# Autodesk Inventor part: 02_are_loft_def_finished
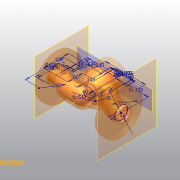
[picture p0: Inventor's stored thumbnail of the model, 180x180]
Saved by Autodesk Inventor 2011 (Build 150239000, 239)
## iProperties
Created: 2002-07
Part Number: 02_are_loft_def_finished
Document SubType Name: Modeling
Designer: Lieven Grauls
Stock Number: 02_are_loft_def_finished
Project: Valve Techcamp 2008
Density: 1 g/cm^3
Surface Area: 777.103 cm^2
Company: Autodesk
Control State: 0
Master: False
Checked Out: False
Shininess: 64.0
Length Units: 11269
Angle Units: 11279
Time Units: 11290
Mass Units: 11283
Length Display Precision: 3
Angle Display Precision: 2
Density: 0.0
Volumn: 0.0
Area: 0.0
PropertySet Name: Model Information
Author: Lieven Grauls
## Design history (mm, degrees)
sketch "Sketch2"
  geometry: L1 (-130, 0)-(-120, 0); L2 (130, 0)-(120, 0); L3 (38.866, 33.5)-(18.866, 33.5); L4 (-50, 103)-(50, 103); L5 (0, -118.6)-(0, 151.6) reference; L6 (-40.156, -25)-(0, -25); A1 r 80 centre (-120, -80) between (-74.375, -14.286) and (-120, 0); A2 r 60 centre (-40.156, 35) between (-74.375, -14.286) and (-40.156, -25); A3 r 70 centre (120, 70) between (70.614, 20.391) and (120, 0); A4 r 45 centre (38.866, -11.5) between (70.614, 20.391) and (38.866, 33.5); 4 further points
  constraints: 10 end point, 8 point on circle, 6 tangent, 4 centre point, 3 horizontal, 2 horizontal alignment, 2 perpendicular, 2 point on line, 1 midpoint, 1 other
  dimensions: "d8" = 130 distance of L1.start point (0, 0); "d9" = 80 radius of A1; "d10" = 60 radius of A2; "d15" = 130 distance of L2.start point (0, 0) (= d8); "d16" = 70 radius of A3; "d61" = 33.5 distance of the line from the sketch origin of L3; "d63" = 45 radius of A4; "d102" = 10 distance of L1.start L1.end; "d103" = 10 distance of L2.start L2.end; "d182" = 20 distance of L3.start L3.end; "d220" = 103 distance of the line from the sketch origin of L4; "d221" = 100 distance of L4.start L4.end; "d249" = 25 distance of the line from the sketch origin of L6
workplane "Work Plane6"
workplane "Work Plane2"
workplane "Work Plane1"
sketch "Sketch5"
  geometry: C1 r 25.5 at (0, 0); 1 further point
  constraints: 1 centre point, 1 coincident
  dimensions: "d24" = 51 diameter of C1
sketch "Sketch6"
  geometry: C1 r 25.5 at (0, 0); 1 further point
  constraints: 1 centre point, 1 coincident
  dimensions: "d25" = 51 diameter of C1
sketch "Sketch11"
  geometry: C1 r 25.5 at (0, 0); 1 further point
  constraints: 1 centre point, 1 coincident
  dimensions: "d104" = 51 diameter of C1 (= d24)
sketch "Sketch7"
  geometry: L1 (0, -22.6)-(0, 135.6) reference; L2 (-32.5, 103)-(-32.5, 74); L3 (-32.5, 74)-(-45.093, 69.417); L4 (-32.5, 8)-(0, 8); L5 (0, 103)-(-32.5, 103); L6 (-46.873, 22.579)-(-39.053, 11.411); L7 (-183.58, 0)-(30.597, 0) reference; A1 r 18 centre (-38.936, 52.502) between (-45.093, 69.417) and (-56.906, 51.462); A2 r 56 centre (-1, 54.699) between (-56.906, 51.462) and (-46.873, 22.579); A3 r 8 centre (-32.5, 16) between (-39.053, 11.411) and (-32.5, 8); 1 further point
  constraints: 10 end point, 6 point on circle, 5 point on line, 5 tangent, 3 centre point, 2 perpendicular, 1 horizontal, 1 parallel
  dimensions: "d28" = 65 diameter of L2 L1; "d30" = 110 deg angle of L2 L3; "d31" = 18 radius of A1; "d32" = 56 radius of A2; "d41" = 55 deg angle of L4 L6; "d65" = 8 radius of A3; "d135" = 103 distance between parallel lines of L7 L5; "d136" = 29 distance of L2.start L2.end; "d137" = 8 distance between parallel lines of L7 L4; "d138" = 1 distance from line of A2.centre L1; "d139" = 65 diameter of A3.centre L1
workplane "Work Plane5"
sketch "Sketch14"
  geometry: L1 (-102.1, 0)-(56.1, 0) reference; L2 (-15, -32)-(-15, 32); L3 (15, 25)-(15, -25); A1 r 56 centre (-12.302, 18.948) between (-9.774, -36.995) and (10.217, -32.325); A2 r 56 centre (-12.302, -18.948) between (10.217, 32.325) and (-9.774, 36.995); A3 r 5 centre (-10, 32) between (-9.774, 36.995) and (-15, 32); A4 r 5 centre (-10, -32) between (-15, -32) and (-9.774, -36.995); A5 r 8 centre (7, 25) between (15, 25) and (10.217, 32.325); A6 r 8 centre (7, -25) between (10.217, -32.325) and (15, -25); 2 further points
  constraints: 12 point on circle, 8 tangent, 6 centre point, 4 end point, 3 equal radius, 1 parallel, 1 perpendicular
  dimensions: "d144" = 15 distance from line of point (0, 0) L2 (= 0.5 x d145); "d145" = 30 distance between parallel lines of L2 L3; "d146" = 56 radius of A1; "d147" = 5 radius of A3; "d148" = 64 distance of A3.centre A4.centre; "d149" = 32 distance from line of L1 A4.centre (= 0.5 x d148); "d150" = 50 distance of A5.centre A6.centre; "d151" = 25 distance from line of L1 A6.centre (= 0.5 x d150); "d152" = 8 radius of A5
workplane "Work Plane10"
sketch "Sketch17"
  geometry: L1 (-9, 25.5)-(-15.5, 32); L2 (-15.5, 32)-(-16.5, 32); L3 (-9, 25.5)-(-9, 0); L4 (-88.753, 0)-(146.625, 0) reference; L5 (0, -7.725)-(0, 46.353) reference; A1 r 32 centre (-16.5, 0) between (-16.5, 32) and (-48.5, 0)
  constraints: 6 end point, 3 point on line, 2 perpendicular, 2 point on circle, 1 centre point, 1 tangent
  dimensions: "d250" = 32 radius of A1; "d252" = 45 deg angle of L3 L1; "d253" = 1 distance of L1.end L2.end; "d286" = 9 distance between parallel lines of L5 L3; "d287" = 25.5 distance from line of L4 L1.start
revolve "Revolution6" sketch "Sketch17" stored, may be unused: angle "d255" = 180 deg
sketch "Sketch19"
  geometry: L1 (32, 1)-(32, 0) reference; L2 (25.5, 7.5)-(32, 1) reference; L3 (-25.5, 7.5)-(25.5, 7.5) reference; L4 (-32, 1)-(-25.5, 7.5) reference; L5 (-32, 0)-(-32, 1) reference; A1 r 32 centre (0, 0) between (-32, 0) and (32, 0) reference; 1 further point
extrude "Extrusion4" join sketch "Sketch19" distance "d257" = 26; taper "d258" = 0 deg
fillet "Fillet11" dims "d259" = 8
extrude "Extrusion5" join sketch "Sketch11" stored distance "d260" = 30; taper "d261" = 0 deg
extrude "Extrusion2" join sketch "Sketch5" distance "d159" = 10; taper "d160" = 0 deg
loft "Loft4" dims "d262" = 10, "d264" = 15, "d266" = 0, "d267" = 90 deg, "d268" = 0, "d269" = 0, "d270" = 204.28206, "d271" = 10, "d272" = 104.55731, "d273" = 10, "d274" = 204.01489, "d275" = 10, "d276" = 61.38852, "d277" = 5.87128, "d278" = 204.19995, "d279" = 9.945, "d280" = 36.81128, "d281" = 3.52068, "d282" = 204.19997, "d283" = 9.95821, "d318" = 90 deg, "d319" = 90 deg, "d320" = 20.91146, "d321" = 2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
  node "Edges4"
  node "Edges5"
extrude "Extrusion3" join sketch "Sketch6" distance "d183" = 10; taper "d184" = 0 deg
loft "Loft3" dims "d187" = 0, "d191" = 0, "d192" = 0, "d193" = 204.28206, "d194" = 10, "d195" = 110.06209, "d196" = 10, "d197" = 220, "d198" = 10.56486, "d199" = 55.03105, "d200" = 5, "d201" = 210, "d202" = 10.0143, "d207" = 10, "d208" = 90 deg, "d209" = 90 deg, "d213" = 0, "d214" = 90 deg
  node "Edges3"
feature "OffsetSrf1" dims "d203" = 8, "d204" = 8
feature "OffsetSrf2" dims "d205" = 8, "d206" = 8
revolve "Revolution5" stored, may be unused: angle "d212" = 90 deg
fillet "Fillet8" dims "d215" = 5
fillet "Fillet13" dims "d311" = 5
sketch "Sketch1"
  geometry: L1 (70, 103)-(70, 55); L2 (57.702, 15.997)-(40.477, -8.604); L3 (0, -42.404)-(0, 138.901) reference; L4 (28.19, -15)-(15, -15); L5 (-198.18, 0)-(118.199, 0) reference; L6 (-198.18, 103)-(118.199, 103) reference; A1 r 68 centre (2, 55) between (57.702, 15.997) and (70, 55); A2 r 15 centre (28.19, 0) between (28.19, -15) and (40.477, -8.604); 1 further point
  constraints: 6 end point, 4 point on circle, 4 tangent, 2 centre point, 1 perpendicular, 1 point on line
  dimensions: "d1" = 140 diameter of L1 L3; "d4" = 68 radius of A1; "d5" = 35 deg angle of L1 L2; "d217" = 15 distance between parallel lines of L4 L5; "d218" = 15 radius of A2; "d222" = 48 distance of L1.start L1.end; "d229" = 15 distance from line of L3 L4.end
feature "RevolutionSrf1" dims angle "d219" = 90 deg
sketch "Sketch8"
  geometry: L1 (-130, 85.5)-(-110, 85.5); L2 (-130, 85.5)-(-132.392, 17.012); L3 (-110, 85.5)-(-108.763, 14.622); L4 (-183.58, 0)-(30.597, 0) reference; L5 (-130, 135.6)-(-130, -22.6) reference
  constraints: 6 end point, 1 parallel, 1 point on line
  dimensions: "d47" = 20 distance of L1.start L1.end; "d223" = 92 deg angle of L4 L2; "d226" = 171 diameter of L1 L4; "d227" = 91 deg angle of L1 L3
feature "RevolutionSrf2" sketch "Sketch8" dims angle "d228" = 90 deg
mirror "Mirror1"
delete_face "Delete Face1"
sketch "Sketch15"
  geometry: L1 (-80, 100)-(-46.5, 100); L2 (-37.013, 96.7)-(-37.013, 60); L3 (-37.013, 60)-(-35.513, 60); L4 (-80, 113)-(-80, 100); L5 (-46.5, 100)-(-46.5, 96.7); L6 (-46.5, 96.7)-(-37.013, 96.7); L7 (0, -22.6)-(0, 135.6) reference; L8 (-183.58, 0)-(30.597, 0) reference; L9 (-35.513, 60)-(-35.513, 0); L10 (-35.513, 0)-(0, 0)
  constraints: 16 end point, 4 perpendicular, 2 vertical, 1 collinear, 1 horizontal, 1 parallel, 1 point on line
  dimensions: "d233" = 3.3 distance between parallel lines of L6 L1; "d237" = 100 distance between parallel lines of L1 L8; "d238" = 60 distance between parallel lines of L8 L3; "d239" = 93 diameter of L5 L7; "d240" = 74.025 diameter of L2 L7; "d241" = 71.025 diameter of L9 L7; "d242" = 160 diameter of L4 L7
sketch "Sketch20"
  geometry: L1 (-128, 77.5)-(-114, 77.5); L2 (-114, 77.5)-(-114, 45); L3 (-114, 45)-(-107, 45); L4 (-107, 45)-(-107, 100.638); L5 (-128, 77.5)-(-128, 48); L6 (-128, 48)-(-130, 48); L7 (-130, 48)-(-130, 0); L8 (0, -22.6)-(0, 135.6) reference; L9 (-183.58, 0)-(30.597, 0) reference; L10 (-130, 0)-(-152.983, 0)
  constraints: 16 end point, 4 parallel, 2 collinear, 2 perpendicular
  dimensions: "d290" = 16 distance between parallel lines of L2 L7; "d292" = 2 distance between parallel lines of L7 L5; "d306" = 155 diameter of L1 L9; "d307" = 96 diameter of L6 L9; "d308" = 90 diameter of L3 L9; "d309" = 130 distance between parallel lines of L8 L7; "d310" = 7 distance of L2.end L3.end
node "Flächen1"
node "Volumenkörpern"
node "Oberflächenkörpern"
node "Flächen2"
node "Flächen3"
node "Flächen4"
node "Flächen5"
node "Flächen6"
feature "RevolutionSrf3"
other parameters: "d285" = -5
